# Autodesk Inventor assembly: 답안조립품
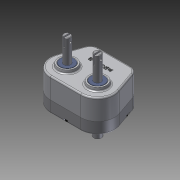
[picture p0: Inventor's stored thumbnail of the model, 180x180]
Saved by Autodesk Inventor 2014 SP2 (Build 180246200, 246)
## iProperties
Created: 2014-12
Part Number: 답안조립품
Document SubType Name: Assembly
Designer: 201-08
Author: 201-08
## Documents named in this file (14)
- C:\Users\201-08\Desktop\441208V1013\답안조립품.iam
- C:\Users\201-08\Desktop\441208V1013\본체.ipt
- C:\Users\201-08\Desktop\441208V1013\베어링- 6203.ipt
- C:\Users\201-08\Desktop\441208V1013\베어링- 6202.ipt
- C:\Users\201-08\Desktop\441208V1013\서브축.ipt
- C:\Users\201-08\Desktop\441208V1013\커버.ipt
- C:\Users\201-08\Desktop\441208V1013\키5x5.ipt
- C:\Users\201-08\Desktop\441208V1013\서브기어.ipt
- C:\Users\201-08\Desktop\441208V1013\멈춤링.ipt
- C:\Users\201-08\Desktop\441208V1013\메인축.ipt
- C:\Users\201-08\Desktop\441208V1013\메인기어.ipt
- C:\Users\201-08\Desktop\441208V1013\오일시일-D-15.ipt
- C:\Users\201-08\Desktop\441208V1013\오일시일-D-17.ipt
- C:\Users\201-08\Desktop\441208V1013\M 5 x 35.ipt
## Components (15 placed, 6 different names)
1. KS B 2023 6203 - 17 x 40 x 12:1
2. KS B 2023 6202 - 15 x 35 x 11:1
3. KS B 2023 6202 - 15 x 35 x 11:2
4. KS B 2023 6203 - 17 x 40 x 12:2
5. KS B 2023 6203 - 17 x 40 x 12:3
6. KS B 1336 17 x 1:1 — 각도:9
7. KS B 1336 17 x 1:2 — 각도:8
8. KS B 2023 6203 - 17 x 40 x 12:4
9. KS B 1336 17 x 1:3 — 각도:7
10. KS B 2804 D D - 15 30 7:1
11. KS B 2804 D D - 15 30 7:2
12. KS B 2804 D D - 17 30 8:1
13. KS B 1003 - 미터 M 5 x 35:1
14. KS B 1003 - 미터 M 5 x 35:2
15. KS B 1003 - 미터 M 5 x 35:3
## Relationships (3: Angle 3)
- 각도:7 [Angle]: KS B 1336 17 x 1:3
- 각도:8 [Angle]: KS B 1336 17 x 1:2
- 각도:9 [Angle]: KS B 1336 17 x 1:1
